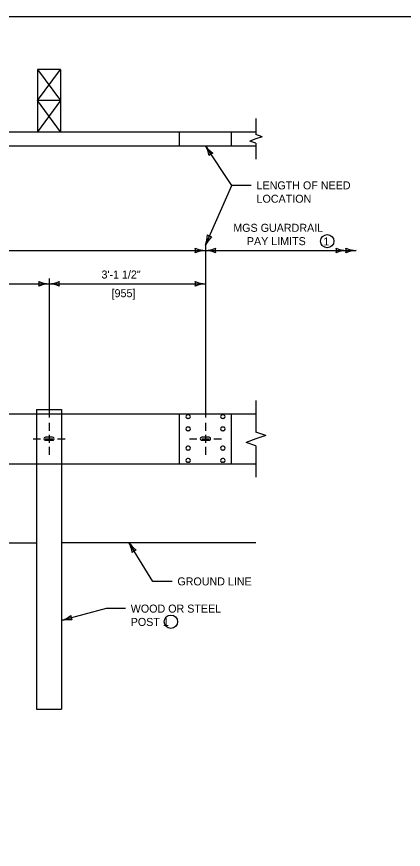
# Model space of a CAD drawing. Extents: x 49991.4 to 50021, y 49987.6 to 50011.4.
# Drawn here: x 50004.62 to 50007.52, y 49992.76 to 49999 of the extents above; entities that cross this region are included whole.
import ezdxf

# ---------------------------------------------------------------- set-up
doc = ezdxf.new("R2010")
doc.units = 0
for name, color, linetype in [('Level 1', 7, 'Continuous'), ('Level 2', 7, 'Continuous'), ('Level 3', 7, 'Continuous'), ('Level 4', 7, 'Continuous'), ('Level 5', 7, 'Continuous'), ('Level 6', 7, 'Continuous')]:
    doc.layers.add(name, color=color, linetype=linetype)

msp = doc.modelspace()

# ---------------------------------------------------------------- linework, layer by layer
at = {"layer": 'Level 1'}
for p, q in [((50004.775, 49998.6042), (50004.775, 49998.3698)), ((50004.775, 49998.6042), (50004.9467, 49998.3698)), ((50004.775, 49998.3698), (50004.9467, 49998.6042)), ((50004.9467, 49998.6042), (50004.775, 49998.6042)), ((50004.9467, 49998.6042), (50004.9467, 49998.3698)), ((50004.775, 49998.3698), (50004.775, 49998.1354)), ((50004.9467, 49998.3698), (50004.775, 49998.1354)), ((50004.9467, 49998.1354), (50004.775, 49998.3698)), ((50004.9467, 49998.3698), (50004.775, 49998.3698)), ((50004.9467, 49998.3698), (50004.775, 49998.3698)), ((50004.9467, 49998.3698), (50004.9467, 49998.1354)), ((50001.2278, 49998.1354), (50006.4114, 49998.1354)), ((50005.8377, 49998.0301), (50005.8377, 49998.1354)), ((50001.5093, 49998.0301), (50006.4114, 49998.0301)), ((50004.767, 49996.0548), (50004.9546, 49996.0548)), ((50004.767, 49996.0548), (50004.767, 49996.0223)), ((50004.9546, 49996.0548), (50004.9546, 49996.0223)), ((50001.1097, 49996.0223), (50006.4116, 49996.0223)), ((50005.8377, 49995.6473), (50005.8377, 49996.0223)), ((50005.906, 49996.0154), (50005.8993, 49996.0154)), ((50005.906, 49995.9876), (50005.8993, 49995.9876)), ((50006.167, 49996.0155), (50006.1603, 49996.0155)), ((50006.167, 49995.9877), (50006.1603, 49995.9877)), ((50005.906, 49995.9236), (50005.8993, 49995.9236)), ((50005.906, 49995.8958), (50005.8993, 49995.8958)), ((50006.167, 49995.9236), (50006.1603, 49995.9236)), ((50006.167, 49995.8958), (50006.1603, 49995.8958)), ((50004.8877, 49995.8477), (50004.834, 49995.8477)), ((50004.834, 49995.8247), (50004.8877, 49995.8247)), ((50006.0595, 49995.8477), (50006.0058, 49995.8477)), ((50006.0058, 49995.8247), (50006.0595, 49995.8247)), ((50005.906, 49995.7794), (50005.8993, 49995.7794)), ((50005.906, 49995.7516), (50005.8993, 49995.7516)), ((50006.167, 49995.7794), (50006.1603, 49995.7794)), ((50006.167, 49995.7516), (50006.1603, 49995.7516)), ((50005.906, 49995.6876), (50005.8993, 49995.6876)), ((50006.167, 49995.6876), (50006.1603, 49995.6876)), ((50001.1097, 49995.6473), (50006.4116, 49995.6473)), ((50004.767, 49995.6473), (50004.767, 49993.8084)), ((50004.9546, 49995.6473), (50004.9546, 49993.8084)), ((50005.906, 49995.6598), (50005.8993, 49995.6598)), ((50006.167, 49995.6598), (50006.1603, 49995.6598)), ((50003.7828, 49995.0551), (50004.767, 49995.0551)), ((50004.9546, 49995.0582), (50006.4116, 49995.0582)), ((50004.767, 49993.8084), (50004.9546, 49993.8084))]:
    msp.add_line(p, q, dxfattribs=at)
msp.add_lwpolyline([(49999.3835, 49998.9992), (50016.7501, 49998.9992), (50016.7501, 49987.7988), (49999.3835, 49987.7988)], close=True, dxfattribs=at)
for centre, major_axis, ratio, start_param, end_param in [((50005.8993, 49996.0015), (0.0139, 0), 0.998676, 1.570796, 4.712389), ((50005.906, 49996.0015), (0.0139, 0), 0.998676, 4.712389, 7.853982), ((50006.1603, 49996.0016), (0.0139, 0), 0.998676, 1.570796, 4.712389), ((50006.167, 49996.0016), (0.0139, 0), 0.998676, 4.712389, 7.853982), ((50005.8993, 49995.9097), (0.0139, 0), 0.998676, 1.570796, 4.712389), ((50005.906, 49995.9097), (0.0139, 0), 0.998676, 4.712389, 7.853982), ((50006.1603, 49995.9097), (0.0139, 0), 0.998676, 1.570796, 4.712389), ((50006.167, 49995.9097), (0.0139, 0), 0.998676, 4.712389, 7.853982), ((50004.834, 49995.8362), (0.0116, 0), 0.988923, 1.570796, 4.712389), ((50004.8877, 49995.8362), (0.0116, 0), 0.995211, 4.712389, 7.853982), ((50006.0058, 49995.8362), (0.0116, 0), 0.988923, 1.570796, 4.712389), ((50006.0595, 49995.8362), (0.0116, 0), 0.995211, 4.712389, 7.853982), ((50005.8993, 49995.7655), (0.0139, 0), 0.998676, 1.570796, 4.712389), ((50005.906, 49995.7655), (0.0139, 0), 0.998676, 4.712389, 7.853982), ((50006.1603, 49995.7655), (0.0139, 0), 0.998676, 1.570796, 4.712389), ((50006.167, 49995.7655), (0.0139, 0), 0.998676, 4.712389, 7.853982), ((50005.8993, 49995.6737), (0.0139, 0), 0.998676, 1.570796, 4.712389), ((50005.906, 49995.6737), (0.0139, 0), 0.998676, 4.712389, 7.853982), ((50006.1603, 49995.6737), (0.0139, 0), 0.998676, 1.570796, 4.712389), ((50006.167, 49995.6737), (0.0139, 0), 0.998676, 4.712389, 7.853982)]:
    msp.add_ellipse(centre, major_axis=major_axis, ratio=ratio, start_param=start_param, end_param=end_param, dxfattribs=at)
at = {"layer": 'Level 2'}
for centre in [(50006.9456, 49997.3168), (50005.7741, 49994.4652)]:
    msp.add_circle(centre, 0.05, dxfattribs=at)
at = {"layer": 'Level 3'}
for p, q in [((50006.2309, 49997.7348), (50006.0327, 49998.0301)), ((50006.0327, 49997.2868), (50006.2309, 49997.7348)), ((50006.3758, 49997.7348), (50006.2309, 49997.7348)), ((50001.3465, 49997.2468), (50006.0327, 49997.2468)), ((50006.0327, 49997.2868), (50006.0327, 49995.9948)), ((50006.0327, 49997.2468), (50007.1616, 49997.2468)), ((50003.689, 49996.9968), (50004.8608, 49996.9968)), ((50004.8608, 49996.9968), (50006.0327, 49996.9968)), ((50004.8608, 49997.0368), (50004.8608, 49995.9948)), ((50005.6376, 49994.7671), (50005.4587, 49995.0582)), ((50005.7825, 49994.7671), (50005.6376, 49994.7671)), ((50005.2881, 49994.5633), (50004.9549, 49994.4743)), ((50005.433, 49994.5633), (50005.2881, 49994.5633))]:
    msp.add_line(p, q, dxfattribs=at)
for centre, radius, start, end in [((50005.8431, 49997.9139), 0.2223, 11.32876, 31.51227), ((50006.2195, 49998.1693), 0.233, 216.70006, 235.94991), ((50006.1041, 49997.9236), 0.0548, 106.01157, 141.73393), ((50005.8152, 49997.3704), 0.233, 338.96851, 358.21836), ((50006.0846, 49997.4041), 0.0548, 228.28002, 264.00238), ((50006.2321, 49997.1886), 0.2223, 133.59721, 153.78072), ((50006.0419, 49997.4689), 0.2223, 247.45601, 267.63952), ((50005.9045, 49997.2468), 0.0548, 342.13882, 17.86118), ((50006.0442, 49997.0141), 0.233, 92.82731, 112.07716), ((50006.0212, 49997.4795), 0.233, 272.82731, 292.07716), ((50006.0235, 49997.0247), 0.2223, 67.45601, 87.63952), ((50006.1609, 49997.2468), 0.0548, 162.13882, 197.86118), ((50007.0973, 49997.4689), 0.2223, 247.45601, 267.63952), ((50006.9599, 49997.2468), 0.0548, 342.13882, 17.86118), ((50007.0997, 49997.0141), 0.233, 92.82731, 112.07716), ((50007.1708, 49997.4689), 0.2223, 247.45601, 267.63952), ((50007.0334, 49997.2468), 0.0548, 342.13882, 17.86118), ((50007.1731, 49997.0141), 0.233, 92.82731, 112.07716), ((50004.87, 49997.2189), 0.2223, 247.45601, 267.63952), ((50004.7326, 49996.9968), 0.0548, 342.13882, 17.86118), ((50004.8723, 49996.7641), 0.233, 92.82731, 112.07716), ((50004.8493, 49997.2295), 0.233, 272.82731, 292.07716), ((50004.8517, 49996.7747), 0.2223, 67.45601, 87.63952), ((50004.989, 49996.9968), 0.0548, 162.13882, 197.86118), ((50006.0419, 49997.2189), 0.2223, 247.45601, 267.63952), ((50005.9045, 49996.9968), 0.0548, 342.13882, 17.86118), ((50006.0442, 49996.7641), 0.233, 92.82731, 112.07716), ((50005.2652, 49994.9487), 0.2223, 9.32467, 29.50818), ((50005.6503, 49995.1909), 0.233, 214.69597, 233.94582), ((50005.5264, 49994.9493), 0.0548, 104.00748, 139.72984), ((50004.883, 49994.6959), 0.233, 287.96723, 307.21708), ((50005.0786, 49994.5078), 0.0548, 177.27874, 213.0011), ((50005.004, 49994.2575), 0.2223, 82.59593, 102.77944)]:
    msp.add_arc(centre, radius, start, end, dxfattribs=at)
at = {"layer": 'Level 4'}
for p, q in [((50006.2277, 49998.0301), (50006.2277, 49998.1354)), ((50004.767, 49996.0223), (50004.767, 49995.6473)), ((50004.9546, 49996.0223), (50004.9546, 49995.6473)), ((50006.2277, 49995.6473), (50006.2277, 49996.0223))]:
    msp.add_line(p, q, dxfattribs=at)
at = {"layer": 'Level 5'}
for p, q in [((50004.8608, 49995.9548), (50004.8608, 49995.8948)), ((50006.0327, 49995.9548), (50006.0327, 49995.8948)), ((50004.8608, 49995.8648), (50004.8608, 49995.8048)), ((50006.0327, 49995.8648), (50006.0327, 49995.8048)), ((50004.7409, 49995.8348), (50004.7971, 49995.8348)), ((50004.8328, 49995.8348), (50004.889, 49995.8348)), ((50004.9247, 49995.835), (50004.9808, 49995.835)), ((50005.9127, 49995.8348), (50005.9689, 49995.8348)), ((50006.0046, 49995.8348), (50006.0608, 49995.8348)), ((50006.0965, 49995.835), (50006.1527, 49995.835)), ((50004.8608, 49995.7748), (50004.8608, 49995.7148)), ((50006.0327, 49995.7748), (50006.0327, 49995.7148))]:
    msp.add_line(p, q, dxfattribs=at)
at = {"layer": 'Level 6'}
for p, q in [((50006.4114, 49998.2354), (50006.4114, 49998.1151)), ((50006.4571, 49998.0989), (50006.4114, 49998.1151)), ((50006.4114, 49998.0827), (50006.3657, 49998.0665)), ((50006.4114, 49998.0503), (50006.3657, 49998.0665)), ((50006.4571, 49998.0989), (50006.4114, 49998.0827)), ((50006.4114, 49998.0503), (50006.4114, 49997.9301)), ((50006.4116, 49996.1223), (50006.4116, 49995.8866)), ((50006.4847, 49995.8607), (50006.4116, 49995.8866)), ((50006.4116, 49995.8348), (50006.3385, 49995.8089)), ((50006.4116, 49995.783), (50006.3385, 49995.8089)), ((50006.4847, 49995.8607), (50006.4116, 49995.8348)), ((50006.4116, 49995.783), (50006.4116, 49995.5473))]:
    msp.add_line(p, q, dxfattribs=at)

# ---------------------------------------------------------------- texts
at = {"layer": 'Level 2'}
for s, p in [('LENGTH OF NEED', (50006.4158, 49997.7048)), ('LOCATION', (50006.4158, 49997.6048)), ('MGS GUARDRAIL', (50006.2415, 49997.3868)), ('PAY LIMITS', (50006.343, 49997.2868)), ('1', (50006.9165, 49997.2846)), ('3\'-1 1/2"', (50005.2539, 49997.0368)), ('[955]', (50005.3296, 49996.8968)), ('GROUND LINE', (50005.8225, 49994.7371)), ('WOOD OR STEEL', (50005.473, 49994.5333)), ('POST 1', (50005.473, 49994.4333))]:
    msp.add_text(s, height=0.06, dxfattribs=at).set_placement(p)

doc.saveas('drawing.dxf')
